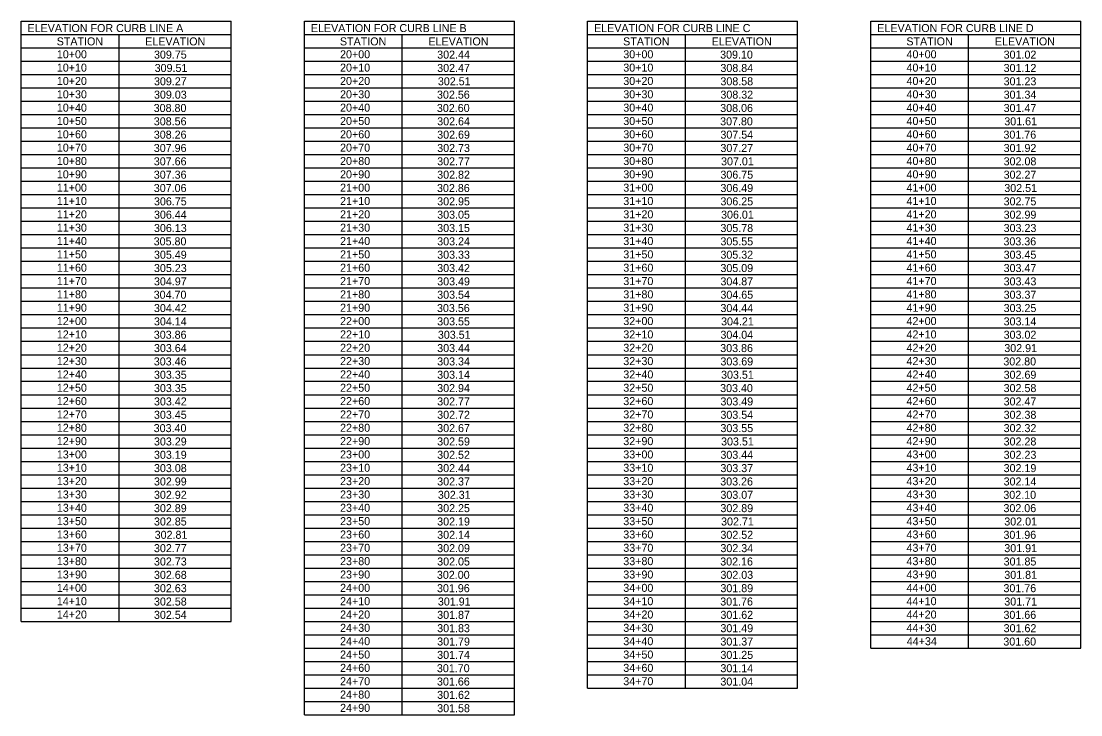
# Model space of a CAD drawing. Extents: x 916322 to 917003, y 328419 to 328887.
# Drawn here: x 916321.6 to 916735.4, y 328616 to 328886.8 of the extents above; entities that cross this region are included whole.
import ezdxf

# ---------------------------------------------------------------- set-up
doc = ezdxf.new("R2010")
doc.units = 0
doc.layers.add('ANNOTATION', color=7, linetype='Continuous')

msp = doc.modelspace()

# ---------------------------------------------------------------- linework, layer by layer
at = {"layer": 'ANNOTATION'}
for p, q in [((916321.61, 328886.83), (916403.61, 328886.83)), ((916321.61, 328652.46), (916321.61, 328886.83)), ((916403.61, 328652.46), (916403.61, 328886.83)), ((916432.22, 328886.83), (916514.22, 328886.83)), ((916432.22, 328616), (916432.22, 328886.83)), ((916514.22, 328616), (916514.22, 328886.83)), ((916542.83, 328886.83), (916624.83, 328886.83)), ((916542.83, 328626.41), (916542.83, 328886.83)), ((916624.83, 328626.41), (916624.83, 328886.83)), ((916653.44, 328886.83), (916735.44, 328886.83)), ((916653.44, 328642.04), (916653.44, 328886.83)), ((916735.44, 328642.04), (916735.44, 328886.83)), ((916321.61, 328881.62), (916403.61, 328881.62)), ((916359.81, 328652.46), (916359.81, 328881.62)), ((916432.22, 328881.62), (916514.22, 328881.62)), ((916470.42, 328616), (916470.42, 328881.62)), ((916542.83, 328881.62), (916624.83, 328881.62)), ((916581.03, 328626.41), (916581.03, 328881.62)), ((916653.44, 328881.62), (916735.44, 328881.62)), ((916691.64, 328642.04), (916691.64, 328881.62)), ((916321.61, 328876.41), (916403.61, 328876.41)), ((916432.22, 328876.41), (916514.22, 328876.41)), ((916542.83, 328876.41), (916624.83, 328876.41)), ((916653.44, 328876.41), (916735.44, 328876.41)), ((916321.61, 328871.21), (916403.61, 328871.21)), ((916432.22, 328871.21), (916514.22, 328871.21)), ((916542.83, 328871.21), (916624.83, 328871.21)), ((916653.44, 328871.21), (916735.44, 328871.21)), ((916321.61, 328866), (916403.61, 328866)), ((916432.22, 328866), (916514.22, 328866)), ((916542.83, 328866), (916624.83, 328866)), ((916653.44, 328866), (916735.44, 328866)), ((916321.61, 328860.79), (916403.61, 328860.79)), ((916432.22, 328860.79), (916514.22, 328860.79)), ((916542.83, 328860.79), (916624.83, 328860.79)), ((916653.44, 328860.79), (916735.44, 328860.79)), ((916321.61, 328855.58), (916403.61, 328855.58)), ((916432.22, 328855.58), (916514.22, 328855.58)), ((916542.83, 328855.58), (916624.83, 328855.58)), ((916653.44, 328855.58), (916735.44, 328855.58)), ((916321.61, 328850.37), (916403.61, 328850.37)), ((916432.22, 328850.37), (916514.22, 328850.37)), ((916542.83, 328850.37), (916624.83, 328850.37)), ((916653.44, 328850.37), (916735.44, 328850.37)), ((916321.61, 328845.16), (916403.61, 328845.16)), ((916432.22, 328845.16), (916514.22, 328845.16)), ((916542.83, 328845.16), (916624.83, 328845.16)), ((916653.44, 328845.16), (916735.44, 328845.16)), ((916321.61, 328839.96), (916403.61, 328839.96)), ((916432.22, 328839.96), (916514.22, 328839.96)), ((916542.83, 328839.96), (916624.83, 328839.96)), ((916653.44, 328839.96), (916735.44, 328839.96)), ((916321.61, 328834.75), (916403.61, 328834.75)), ((916432.22, 328834.75), (916514.22, 328834.75)), ((916542.83, 328834.75), (916624.83, 328834.75)), ((916653.44, 328834.75), (916735.44, 328834.75)), ((916321.61, 328829.54), (916403.61, 328829.54)), ((916432.22, 328829.54), (916514.22, 328829.54)), ((916542.83, 328829.54), (916624.83, 328829.54)), ((916653.44, 328829.54), (916735.44, 328829.54)), ((916321.61, 328824.33), (916403.61, 328824.33)), ((916432.22, 328824.33), (916514.22, 328824.33)), ((916542.83, 328824.33), (916624.83, 328824.33)), ((916653.44, 328824.33), (916735.44, 328824.33)), ((916321.61, 328819.12), (916403.61, 328819.12)), ((916432.22, 328819.12), (916514.22, 328819.12)), ((916542.83, 328819.12), (916624.83, 328819.12)), ((916653.44, 328819.12), (916735.44, 328819.12)), ((916321.61, 328813.91), (916403.61, 328813.91)), ((916432.22, 328813.91), (916514.22, 328813.91)), ((916542.83, 328813.91), (916624.83, 328813.91)), ((916653.44, 328813.91), (916735.44, 328813.91)), ((916321.61, 328808.71), (916403.61, 328808.71)), ((916432.22, 328808.71), (916514.22, 328808.71)), ((916542.83, 328808.71), (916624.83, 328808.71)), ((916653.44, 328808.71), (916735.44, 328808.71)), ((916321.61, 328803.5), (916403.61, 328803.5)), ((916432.22, 328803.5), (916514.22, 328803.5)), ((916542.83, 328803.5), (916624.83, 328803.5)), ((916653.44, 328803.5), (916735.44, 328803.5)), ((916321.61, 328798.29), (916403.61, 328798.29)), ((916432.22, 328798.29), (916514.22, 328798.29)), ((916542.83, 328798.29), (916624.83, 328798.29)), ((916653.44, 328798.29), (916735.44, 328798.29)), ((916321.61, 328793.08), (916403.61, 328793.08)), ((916432.22, 328793.08), (916514.22, 328793.08)), ((916542.83, 328793.08), (916624.83, 328793.08)), ((916653.44, 328793.08), (916735.44, 328793.08)), ((916321.61, 328787.87), (916403.61, 328787.87)), ((916432.22, 328787.87), (916514.22, 328787.87)), ((916542.83, 328787.87), (916624.83, 328787.87)), ((916653.44, 328787.87), (916735.44, 328787.87)), ((916321.61, 328782.66), (916403.61, 328782.66)), ((916432.22, 328782.66), (916514.22, 328782.66)), ((916542.83, 328782.66), (916624.83, 328782.66)), ((916653.44, 328782.66), (916735.44, 328782.66)), ((916321.61, 328777.46), (916403.61, 328777.46)), ((916432.22, 328777.46), (916514.22, 328777.46)), ((916542.83, 328777.46), (916624.83, 328777.46)), ((916653.44, 328777.46), (916735.44, 328777.46)), ((916321.61, 328772.25), (916403.61, 328772.25)), ((916432.22, 328772.25), (916514.22, 328772.25)), ((916542.83, 328772.25), (916624.83, 328772.25)), ((916653.44, 328772.25), (916735.44, 328772.25)), ((916321.61, 328767.04), (916403.61, 328767.04)), ((916432.22, 328767.04), (916514.22, 328767.04)), ((916542.83, 328767.04), (916624.83, 328767.04)), ((916653.44, 328767.04), (916735.44, 328767.04)), ((916321.61, 328761.83), (916403.61, 328761.83)), ((916432.22, 328761.83), (916514.22, 328761.83)), ((916542.83, 328761.83), (916624.83, 328761.83)), ((916653.44, 328761.83), (916735.44, 328761.83)), ((916321.61, 328756.62), (916403.61, 328756.62)), ((916432.22, 328756.62), (916514.22, 328756.62)), ((916542.83, 328756.62), (916624.83, 328756.62)), ((916653.44, 328756.62), (916735.44, 328756.62)), ((916321.61, 328751.41), (916403.61, 328751.41)), ((916432.22, 328751.41), (916514.22, 328751.41)), ((916542.83, 328751.41), (916624.83, 328751.41)), ((916653.44, 328751.41), (916735.44, 328751.41)), ((916321.61, 328746.21), (916403.61, 328746.21)), ((916432.22, 328746.21), (916514.22, 328746.21)), ((916542.83, 328746.21), (916624.83, 328746.21)), ((916653.44, 328746.21), (916735.44, 328746.21)), ((916321.61, 328741), (916403.61, 328741)), ((916432.22, 328741), (916514.22, 328741)), ((916542.83, 328741), (916624.83, 328741)), ((916653.44, 328741), (916735.44, 328741)), ((916321.61, 328735.79), (916403.61, 328735.79)), ((916432.22, 328735.79), (916514.22, 328735.79)), ((916542.83, 328735.79), (916624.83, 328735.79)), ((916653.44, 328735.79), (916735.44, 328735.79)), ((916321.61, 328730.58), (916403.61, 328730.58)), ((916432.22, 328730.58), (916514.22, 328730.58)), ((916542.83, 328730.58), (916624.83, 328730.58)), ((916653.44, 328730.58), (916735.44, 328730.58)), ((916321.61, 328725.37), (916403.61, 328725.37)), ((916432.22, 328725.37), (916514.22, 328725.37)), ((916542.83, 328725.37), (916624.83, 328725.37)), ((916653.44, 328725.37), (916735.44, 328725.37)), ((916321.61, 328720.16), (916403.61, 328720.16)), ((916432.22, 328720.16), (916514.22, 328720.16)), ((916542.83, 328720.16), (916624.83, 328720.16)), ((916653.44, 328720.16), (916735.44, 328720.16)), ((916321.61, 328714.96), (916403.61, 328714.96)), ((916432.22, 328714.96), (916514.22, 328714.96)), ((916542.83, 328714.96), (916624.83, 328714.96)), ((916653.44, 328714.96), (916735.44, 328714.96)), ((916321.61, 328709.75), (916403.61, 328709.75)), ((916432.22, 328709.75), (916514.22, 328709.75)), ((916542.83, 328709.75), (916624.83, 328709.75)), ((916653.44, 328709.75), (916735.44, 328709.75)), ((916321.61, 328704.54), (916403.61, 328704.54)), ((916432.22, 328704.54), (916514.22, 328704.54)), ((916542.83, 328704.54), (916624.83, 328704.54)), ((916653.44, 328704.54), (916735.44, 328704.54)), ((916321.61, 328699.33), (916403.61, 328699.33)), ((916432.22, 328699.33), (916514.22, 328699.33)), ((916542.83, 328699.33), (916624.83, 328699.33)), ((916653.44, 328699.33), (916735.44, 328699.33)), ((916321.61, 328694.12), (916403.61, 328694.12)), ((916432.22, 328694.12), (916514.22, 328694.12)), ((916542.83, 328694.12), (916624.83, 328694.12)), ((916653.44, 328694.12), (916735.44, 328694.12)), ((916321.61, 328688.91), (916403.61, 328688.91)), ((916432.22, 328688.91), (916514.22, 328688.91)), ((916542.83, 328688.91), (916624.83, 328688.91)), ((916653.44, 328688.91), (916735.44, 328688.91)), ((916321.61, 328683.71), (916403.61, 328683.71)), ((916432.22, 328683.71), (916514.22, 328683.71)), ((916542.83, 328683.71), (916624.83, 328683.71)), ((916653.44, 328683.71), (916735.44, 328683.71)), ((916321.61, 328678.5), (916403.61, 328678.5)), ((916432.22, 328678.5), (916514.22, 328678.5)), ((916542.83, 328678.5), (916624.83, 328678.5)), ((916653.44, 328678.5), (916735.44, 328678.5)), ((916321.61, 328673.29), (916403.61, 328673.29)), ((916432.22, 328673.29), (916514.22, 328673.29)), ((916542.83, 328673.29), (916624.83, 328673.29)), ((916653.44, 328673.29), (916735.44, 328673.29)), ((916321.61, 328668.08), (916403.61, 328668.08)), ((916432.22, 328668.08), (916514.22, 328668.08)), ((916542.83, 328668.08), (916624.83, 328668.08)), ((916653.44, 328668.08), (916735.44, 328668.08)), ((916321.61, 328662.87), (916403.61, 328662.87)), ((916432.22, 328662.87), (916514.22, 328662.87)), ((916542.83, 328662.87), (916624.83, 328662.87)), ((916653.44, 328662.87), (916735.44, 328662.87)), ((916321.61, 328657.66), (916403.61, 328657.66)), ((916432.22, 328657.66), (916514.22, 328657.66)), ((916542.83, 328657.66), (916624.83, 328657.66)), ((916653.44, 328657.66), (916735.44, 328657.66)), ((916321.61, 328652.46), (916403.61, 328652.46)), ((916432.22, 328652.46), (916514.22, 328652.46)), ((916542.83, 328652.46), (916624.83, 328652.46)), ((916653.44, 328652.46), (916735.44, 328652.46)), ((916432.22, 328647.25), (916514.22, 328647.25)), ((916542.83, 328647.25), (916624.83, 328647.25)), ((916653.44, 328647.25), (916735.44, 328647.25)), ((916432.22, 328642.04), (916514.22, 328642.04)), ((916542.83, 328642.04), (916624.83, 328642.04)), ((916653.44, 328642.04), (916735.44, 328642.04)), ((916432.22, 328636.83), (916514.22, 328636.83)), ((916542.83, 328636.83), (916624.83, 328636.83)), ((916432.22, 328631.62), (916514.22, 328631.62)), ((916542.83, 328631.62), (916624.83, 328631.62)), ((916432.22, 328626.41), (916514.22, 328626.41)), ((916542.83, 328626.41), (916624.83, 328626.41)), ((916432.22, 328621.21), (916514.22, 328621.21)), ((916432.22, 328616), (916514.22, 328616))]:
    msp.add_line(p, q, dxfattribs=at)

# ---------------------------------------------------------------- texts
for s, p in [('ELEVATION FOR CURB LINE A', (916324.07, 328882.59)), ('ELEVATION FOR CURB LINE B', (916434.74, 328882.59)), ('ELEVATION FOR CURB LINE C', (916545.34, 328882.59)), ('ELEVATION FOR CURB LINE D', (916655.95, 328882.59)), ('STATION', (916335.48, 328877.38)), ('ELEVATION', (916370.05, 328877.38)), ('STATION', (916446.09, 328877.38)), ('ELEVATION', (916480.66, 328877.38)), ('STATION', (916556.7, 328877.38)), ('ELEVATION', (916591.27, 328877.38)), ('STATION', (916667.31, 328877.38)), ('ELEVATION', (916701.88, 328877.38))]:
    msp.add_text(s, height=3.125, rotation=360, dxfattribs=at).set_placement(p)
for s, p in [('10+00', (916335.54, 328872.35)), ('309.75', (916373.47, 328872.22)), ('20+00', (916446.15, 328872.35)), ('302.44', (916484.08, 328872.22)), ('30+00', (916556.76, 328872.35)), ('309.10', (916594.58, 328872.22)), ('40+00', (916667.37, 328872.35)), ('301.02', (916705.3, 328872.22)), ('10+10', (916335.54, 328867.14)), ('309.51', (916373.74, 328867.01)), ('20+10', (916446.15, 328867.14)), ('302.47', (916484.08, 328867.01)), ('30+10', (916556.76, 328867.14)), ('308.84', (916594.69, 328867.01)), ('40+10', (916667.37, 328867.14)), ('301.12', (916705.3, 328867.01)), ('10+20', (916335.54, 328861.93)), ('309.27', (916373.47, 328861.8)), ('20+20', (916446.15, 328861.93)), ('302.51', (916484.35, 328861.8)), ('30+20', (916556.76, 328861.93)), ('308.58', (916594.69, 328861.8)), ('40+20', (916667.37, 328861.93)), ('301.23', (916705.3, 328861.8)), ('10+30', (916335.54, 328856.72)), ('309.03', (916373.47, 328856.59)), ('20+30', (916446.15, 328856.72)), ('302.56', (916484.01, 328856.59)), ('30+30', (916556.76, 328856.72)), ('308.32', (916594.69, 328856.59)), ('40+30', (916667.37, 328856.72)), ('301.34', (916705.3, 328856.59)), ('10+40', (916335.54, 328851.51)), ('308.80', (916373.36, 328851.38)), ('20+40', (916446.15, 328851.51)), ('302.60', (916483.97, 328851.38)), ('30+40', (916556.76, 328851.51)), ('308.06', (916594.62, 328851.38)), ('40+40', (916667.37, 328851.51)), ('301.47', (916705.3, 328851.38)), ('10+50', (916335.54, 328846.3)), ('308.56', (916373.4, 328846.17)), ('20+50', (916446.15, 328846.3)), ('302.64', (916484.08, 328846.17)), ('30+50', (916556.76, 328846.3)), ('307.80', (916594.58, 328846.17)), ('40+50', (916667.37, 328846.3)), ('301.61', (916705.56, 328846.17)), ('10+60', (916335.54, 328841.1)), ('308.26', (916373.4, 328840.97)), ('20+60', (916446.15, 328841.1)), ('302.69', (916484.08, 328840.97)), ('30+60', (916556.76, 328841.1)), ('307.54', (916594.69, 328840.97)), ('40+60', (916667.37, 328841.1)), ('301.76', (916705.23, 328840.97)), ('10+70', (916335.54, 328835.89)), ('307.96', (916373.4, 328835.76)), ('20+70', (916446.15, 328835.89)), ('302.73', (916484.08, 328835.76)), ('30+70', (916556.76, 328835.89)), ('307.27', (916594.69, 328835.76)), ('40+70', (916667.37, 328835.89)), ('301.92', (916705.3, 328835.76)), ('10+80', (916335.54, 328830.68)), ('307.66', (916373.4, 328830.55)), ('20+80', (916446.15, 328830.68)), ('302.77', (916484.08, 328830.55)), ('30+80', (916556.76, 328830.68)), ('307.01', (916594.95, 328830.55)), ('40+80', (916667.37, 328830.68)), ('302.08', (916705.3, 328830.55)), ('10+90', (916335.54, 328825.47)), ('307.36', (916373.4, 328825.34)), ('20+90', (916446.15, 328825.47)), ('302.82', (916484.08, 328825.34)), ('30+90', (916556.76, 328825.47)), ('306.75', (916594.69, 328825.34)), ('40+90', (916667.37, 328825.47)), ('302.27', (916705.3, 328825.34)), ('11+00', (916335.54, 328820.26)), ('307.06', (916373.4, 328820.13)), ('21+00', (916446.15, 328820.26)), ('302.86', (916484.01, 328820.13)), ('31+00', (916556.76, 328820.26)), ('306.49', (916594.69, 328820.13)), ('41+00', (916667.37, 328820.26)), ('302.51', (916705.56, 328820.13)), ('11+10', (916335.54, 328815.05)), ('306.75', (916373.47, 328814.92)), ('21+10', (916446.15, 328815.05)), ('302.95', (916484.08, 328814.92)), ('31+10', (916556.76, 328815.05)), ('306.25', (916594.69, 328814.92)), ('41+10', (916667.37, 328815.05)), ('302.75', (916705.3, 328814.92)), ('11+20', (916335.54, 328809.85)), ('306.44', (916373.47, 328809.72)), ('21+20', (916446.15, 328809.85)), ('303.05', (916484.08, 328809.72)), ('31+20', (916556.76, 328809.85)), ('306.01', (916594.95, 328809.72)), ('41+20', (916667.37, 328809.85)), ('302.99', (916705.3, 328809.72)), ('11+30', (916335.54, 328804.64)), ('306.13', (916373.47, 328804.51)), ('21+30', (916446.15, 328804.64)), ('303.15', (916484.08, 328804.51)), ('31+30', (916556.76, 328804.64)), ('305.78', (916594.69, 328804.51)), ('41+30', (916667.37, 328804.64)), ('303.23', (916705.3, 328804.51)), ('11+40', (916335.54, 328799.43)), ('305.80', (916373.36, 328799.3)), ('21+40', (916446.15, 328799.43)), ('303.24', (916484.08, 328799.3)), ('31+40', (916556.76, 328799.43)), ('305.55', (916594.69, 328799.3)), ('41+40', (916667.37, 328799.43)), ('303.36', (916705.23, 328799.3)), ('11+50', (916335.54, 328794.22)), ('305.49', (916373.47, 328794.09)), ('21+50', (916446.15, 328794.22)), ('303.33', (916484.08, 328794.09)), ('31+50', (916556.76, 328794.22)), ('305.32', (916594.69, 328794.09)), ('41+50', (916667.37, 328794.22)), ('303.45', (916705.3, 328794.09)), ('11+60', (916335.54, 328789.01)), ('305.23', (916373.47, 328788.88)), ('21+60', (916446.15, 328789.01)), ('303.42', (916484.08, 328788.88)), ('31+60', (916556.76, 328789.01)), ('305.09', (916594.69, 328788.88)), ('41+60', (916667.37, 328789.01)), ('303.47', (916705.3, 328788.88)), ('11+70', (916335.54, 328783.8)), ('304.97', (916373.47, 328783.67)), ('21+70', (916446.15, 328783.8)), ('303.49', (916484.08, 328783.67)), ('31+70', (916556.76, 328783.8)), ('304.87', (916594.69, 328783.67)), ('41+70', (916667.37, 328783.8)), ('303.43', (916705.3, 328783.67)), ('11+80', (916335.54, 328778.6)), ('304.70', (916373.36, 328778.47)), ('21+80', (916446.15, 328778.6)), ('303.54', (916484.08, 328778.47)), ('31+80', (916556.76, 328778.6)), ('304.65', (916594.69, 328778.47)), ('41+80', (916667.37, 328778.6)), ('303.37', (916705.3, 328778.47)), ('11+90', (916335.54, 328773.39)), ('304.42', (916373.47, 328773.26)), ('21+90', (916446.15, 328773.39)), ('303.56', (916484.01, 328773.26)), ('31+90', (916556.76, 328773.39)), ('304.44', (916594.69, 328773.26)), ('41+90', (916667.37, 328773.39)), ('303.25', (916705.3, 328773.26)), ('12+00', (916335.54, 328768.18)), ('22+00', (916446.15, 328768.18)), ('32+00', (916556.76, 328768.18)), ('42+00', (916667.37, 328768.18)), ('304.14', (916373.47, 328768.05)), ('303.55', (916484.08, 328768.05)), ('304.21', (916594.95, 328768.05)), ('303.14', (916705.3, 328768.05)), ('12+10', (916335.54, 328762.97)), ('303.86', (916373.4, 328762.84)), ('22+10', (916446.15, 328762.97)), ('303.51', (916484.35, 328762.84)), ('32+10', (916556.76, 328762.97)), ('304.04', (916594.69, 328762.84)), ('42+10', (916667.37, 328762.97)), ('303.02', (916705.3, 328762.84)), ('12+20', (916335.54, 328757.76)), ('303.64', (916373.47, 328757.63)), ('22+20', (916446.15, 328757.76)), ('303.44', (916484.08, 328757.63)), ('32+20', (916556.76, 328757.76)), ('303.86', (916594.62, 328757.63)), ('42+20', (916667.37, 328757.76)), ('302.91', (916705.56, 328757.63)), ('12+30', (916335.54, 328752.55)), ('303.46', (916373.4, 328752.42)), ('22+30', (916446.15, 328752.55)), ('303.34', (916484.08, 328752.42)), ('32+30', (916556.76, 328752.55)), ('303.69', (916594.69, 328752.42)), ('42+30', (916667.37, 328752.55)), ('302.80', (916705.19, 328752.42)), ('12+40', (916335.54, 328747.35)), ('303.35', (916373.47, 328747.22)), ('22+40', (916446.15, 328747.35)), ('303.14', (916484.08, 328747.22)), ('32+40', (916556.76, 328747.35)), ('303.51', (916594.95, 328747.22)), ('42+40', (916667.37, 328747.35)), ('302.69', (916705.3, 328747.22)), ('12+50', (916335.54, 328742.14)), ('303.35', (916373.47, 328742.01)), ('22+50', (916446.15, 328742.14)), ('302.94', (916484.08, 328742.01)), ('32+50', (916556.76, 328742.14)), ('303.40', (916594.58, 328742.01)), ('42+50', (916667.37, 328742.14)), ('302.58', (916705.3, 328742.01)), ('12+60', (916335.54, 328736.93)), ('303.42', (916373.47, 328736.8)), ('22+60', (916446.15, 328736.93)), ('302.77', (916484.08, 328736.8)), ('32+60', (916556.76, 328736.93)), ('303.49', (916594.69, 328736.8)), ('42+60', (916667.37, 328736.93)), ('302.47', (916705.3, 328736.8)), ('12+70', (916335.54, 328731.72)), ('303.45', (916373.47, 328731.59)), ('22+70', (916446.15, 328731.72)), ('302.72', (916484.08, 328731.59)), ('32+70', (916556.76, 328731.72)), ('303.54', (916594.69, 328731.59)), ('42+70', (916667.37, 328731.72)), ('302.38', (916705.3, 328731.59)), ('12+80', (916335.54, 328726.51)), ('303.40', (916373.36, 328726.38)), ('22+80', (916446.15, 328726.51)), ('302.67', (916484.08, 328726.38)), ('32+80', (916556.76, 328726.51)), ('303.55', (916594.69, 328726.38)), ('42+80', (916667.37, 328726.51)), ('302.32', (916705.3, 328726.38)), ('12+90', (916335.54, 328721.3)), ('303.29', (916373.47, 328721.17)), ('22+90', (916446.15, 328721.3)), ('302.59', (916484.08, 328721.17)), ('32+90', (916556.76, 328721.3)), ('303.51', (916594.95, 328721.17)), ('42+90', (916667.37, 328721.3)), ('302.28', (916705.3, 328721.17)), ('13+00', (916335.54, 328716.1)), ('303.19', (916373.47, 328715.97)), ('23+00', (916446.15, 328716.1)), ('302.52', (916484.08, 328715.97)), ('33+00', (916556.76, 328716.1)), ('303.44', (916594.69, 328715.97)), ('43+00', (916667.37, 328716.1)), ('302.23', (916705.3, 328715.97)), ('13+10', (916335.54, 328710.89)), ('303.08', (916373.47, 328710.76)), ('23+10', (916446.15, 328710.89)), ('302.44', (916484.08, 328710.76)), ('33+10', (916556.76, 328710.89)), ('303.37', (916594.69, 328710.76)), ('43+10', (916667.37, 328710.89)), ('302.19', (916705.3, 328710.76)), ('13+20', (916335.54, 328705.68)), ('302.99', (916373.47, 328705.55)), ('23+20', (916446.15, 328705.68)), ('302.37', (916484.08, 328705.55)), ('33+20', (916556.76, 328705.68)), ('303.26', (916594.62, 328705.55)), ('43+20', (916667.37, 328705.68)), ('302.14', (916705.3, 328705.55)), ('13+30', (916335.54, 328700.47)), ('302.92', (916373.47, 328700.34)), ('23+30', (916446.15, 328700.47)), ('302.31', (916484.35, 328700.34)), ('33+30', (916556.76, 328700.47)), ('303.07', (916594.69, 328700.34)), ('43+30', (916667.37, 328700.47)), ('302.10', (916705.19, 328700.34)), ('13+40', (916335.54, 328695.26)), ('302.89', (916373.47, 328695.13)), ('23+40', (916446.15, 328695.26)), ('302.25', (916484.08, 328695.13)), ('33+40', (916556.76, 328695.26)), ('302.89', (916594.69, 328695.13)), ('43+40', (916667.37, 328695.26)), ('302.06', (916705.23, 328695.13)), ('13+50', (916335.54, 328690.05)), ('302.85', (916373.47, 328689.92)), ('23+50', (916446.15, 328690.05)), ('302.19', (916484.08, 328689.92)), ('33+50', (916556.76, 328690.05)), ('302.71', (916594.95, 328689.92)), ('43+50', (916667.37, 328690.05)), ('302.01', (916705.56, 328689.92)), ('13+60', (916335.54, 328684.85)), ('302.81', (916373.74, 328684.72)), ('23+60', (916446.15, 328684.85)), ('302.14', (916484.08, 328684.72)), ('33+60', (916556.76, 328684.85)), ('302.52', (916594.69, 328684.72)), ('43+60', (916667.37, 328684.85)), ('301.96', (916705.23, 328684.72)), ('13+70', (916335.54, 328679.64)), ('302.77', (916373.47, 328679.51)), ('23+70', (916446.15, 328679.64)), ('302.09', (916484.08, 328679.51)), ('33+70', (916556.76, 328679.64)), ('302.34', (916594.69, 328679.51)), ('43+70', (916667.37, 328679.64)), ('301.91', (916705.56, 328679.51)), ('13+80', (916335.54, 328674.43)), ('302.73', (916373.47, 328674.3)), ('23+80', (916446.15, 328674.43)), ('302.05', (916484.08, 328674.3)), ('33+80', (916556.76, 328674.43)), ('302.16', (916594.62, 328674.3)), ('43+80', (916667.37, 328674.43)), ('301.85', (916705.3, 328674.3)), ('13+90', (916335.54, 328669.22)), ('302.68', (916373.47, 328669.09)), ('23+90', (916446.15, 328669.22)), ('302.00', (916483.97, 328669.09)), ('33+90', (916556.76, 328669.22)), ('302.03', (916594.69, 328669.09)), ('43+90', (916667.37, 328669.22)), ('301.81', (916705.56, 328669.09)), ('14+00', (916335.54, 328664.01)), ('302.63', (916373.47, 328663.88)), ('24+00', (916446.15, 328664.01)), ('301.96', (916484.01, 328663.88)), ('34+00', (916556.76, 328664.01)), ('301.89', (916594.69, 328663.88)), ('44+00', (916667.37, 328664.01)), ('301.76', (916705.23, 328663.88)), ('14+10', (916335.54, 328658.8)), ('302.58', (916373.47, 328658.67)), ('24+10', (916446.15, 328658.8)), ('301.91', (916484.35, 328658.67)), ('34+10', (916556.76, 328658.8)), ('301.76', (916594.62, 328658.67)), ('44+10', (916667.37, 328658.8)), ('301.71', (916705.56, 328658.67)), ('14+20', (916335.54, 328653.6)), ('302.54', (916373.47, 328653.47)), ('24+20', (916446.15, 328653.6)), ('301.87', (916484.08, 328653.47)), ('34+20', (916556.76, 328653.6)), ('301.62', (916594.69, 328653.47)), ('44+20', (916667.37, 328653.6)), ('301.66', (916705.23, 328653.47)), ('24+30', (916446.15, 328648.39)), ('301.83', (916484.08, 328648.26)), ('34+30', (916556.76, 328648.39)), ('301.49', (916594.69, 328648.26)), ('44+30', (916667.37, 328648.39)), ('301.62', (916705.3, 328648.26)), ('24+40', (916446.15, 328643.18)), ('301.79', (916484.08, 328643.05)), ('34+40', (916556.76, 328643.18)), ('301.37', (916594.69, 328643.05)), ('44+34', (916667.49, 328643.18)), ('301.60', (916705.19, 328643.05)), ('24+50', (916446.15, 328637.97)), ('301.74', (916484.08, 328637.84)), ('34+50', (916556.76, 328637.97)), ('301.25', (916594.69, 328637.84)), ('24+60', (916446.15, 328632.76)), ('301.70', (916483.97, 328632.63)), ('34+60', (916556.76, 328632.76)), ('301.14', (916594.69, 328632.63)), ('24+70', (916446.15, 328627.55)), ('301.66', (916484.01, 328627.42)), ('34+70', (916556.76, 328627.55)), ('301.04', (916594.69, 328627.42)), ('24+80', (916446.15, 328622.35)), ('301.62', (916484.08, 328622.22)), ('24+90', (916446.15, 328617.14)), ('301.58', (916484.08, 328617.01))]:
    msp.add_text(s, height=3.125, dxfattribs=at).set_placement(p)

doc.saveas('drawing.dxf')
